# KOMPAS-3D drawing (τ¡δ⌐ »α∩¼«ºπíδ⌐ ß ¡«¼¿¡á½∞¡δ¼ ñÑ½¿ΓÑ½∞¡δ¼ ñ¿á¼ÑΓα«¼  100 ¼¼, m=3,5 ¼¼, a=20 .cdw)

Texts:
  Долбяк чашечный прямозубый с номинальным делительным диаметром  100 мм, m=3,5 мм, ^(Symbol type A)97~=20@1~
  Ганжа Семен Сергеевич, гр. 235
  Рабочий чертеж зуборезного долбяка с номинальным  делительным диаметром 100 мм
  Рабочий чертеж зуборезного долбяка с номинальным
  делительным диаметром 100 мм
  Текст на чертеже
  Размерные надписи
  Шероховатость
  Линия-выноска #1
  Линия-выноска #2
  Линия-выноска #3
  Отклонения формы и база
  Заголовок таблицы
  Ячейка таблицы
  Стрелка вида
  Обозначение изменения
  Фигурная скобка
  Номер узла
  Марка координационной оси
  VRCB
  Выносная надпись
  Обозначение узла
  Марка/позиционное обозначение с линией-выноской
  Марка/позиционное обозначение на линии
  Марка/позиционное обозначение без линии-выноски
  Additional DXF text style 0
  cs 2
  cs 3
  cs 4
  Исходное
  сечение
  Symbol type A
  cs 1
  Делительная
  окружность
  Долбяки должны удовлетворять требованиям ГОСТ 9323-79
  Твердость HRC э  62...65
  Эксцентриситет d  относительно оси отверстия не более 0,01
  мм (биение 0,02 мм)
  Допуск на профиль рабочей части зуба долбяка не должен
  превышать 0,01 мм
  Отклонение D  от номинала не должно превышать минус 1,0 мм
  Маркировать: модуль число зубьев, номинальный делительный
  диаметр, угол зацепления, класс точности долбяка, марку стали,
  год выпуска и товарный знак завода-изготовителя (
  CONTINUOUS7
  Долбяк чашечный
  прямозубый с номинальным
  делительным диаметром
  Сталь Р18 ГОСТ 19265-73
Dimensions and other numbers on the sheet: 7; 5; 22,5; 32; 0,25; 0,008/ 48; 0,05/ 98; 0,005; 2; 12; 1; 1,0; 0,5; 0,015; 0,3; 2 фаски; 0,6; 44,45; 63; 67; 88,91; 107,10; 98; 0,125; 5,50; 4,55; 0.25; 2,0; 1:1; 100 мм, m=3,5 мм,  =20; 3; 0; 4; 6; 8; 9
